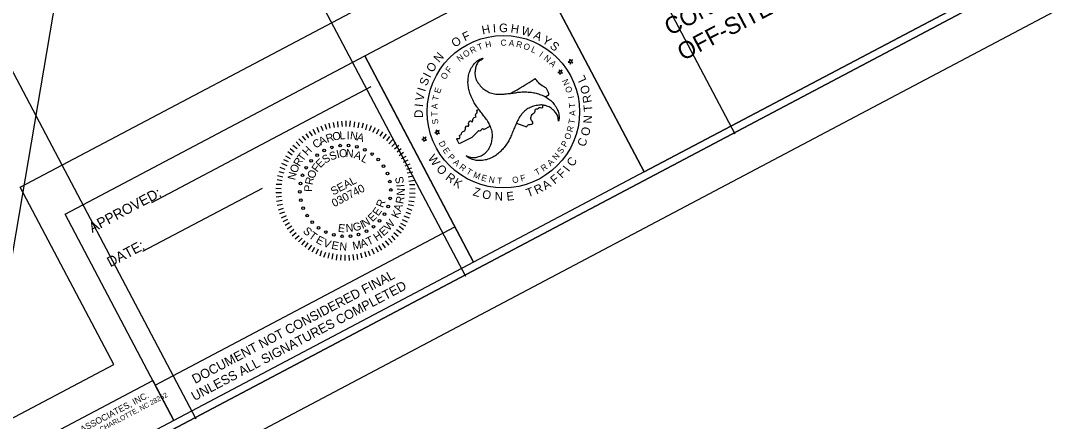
# Model space of a CAD drawing. Extents: x 1487176 to 2935813, y 497724 to 1002340.
# Drawn here: x 1489024 to 1489641, y 498480 to 498716 of the extents above; entities that cross this region are included whole.
import ezdxf

# ---------------------------------------------------------------- set-up
doc = ezdxf.new("R2010")
doc.units = 0
for name, color, linetype in [('DEV BORDER CELL', 7, 'Continuous'), ('DEV DOT SWIRL SEAL CELL', 7, 'Continuous'), ('Old_Level_9', 7, 'Continuous'), ('Prop Grid Mask', 7, 'Continuous'), ('Scratch_Level_0', 7, 'Continuous'), ('Scratch_Level_1', 7, 'Continuous'), ('Scratch_Level_3', 7, 'Continuous'), ('Scratch_Level_5', 7, 'Continuous'), ('Sheet Block Title CELL', 7, 'Continuous'), ('Sheet Plot Border Outside CELL', 7, 'Continuous'), ('Sheet Sticker Exception Certification CELL', 7, 'Continuous'), ('Text', 7, 'Continuous')]:
    doc.layers.add(name, color=color, linetype=linetype)

msp = doc.modelspace()

# ---------------------------------------------------------------- linework, layer by layer
at = {"layer": 'DEV BORDER CELL'}
for p, q in [((1489101.26, 498608.61), (1489230.66, 498676.94)), ((1489237.93, 498674.2), (1489291.16, 498573.39)), ((1489096.01, 498579.75), (1489166.57, 498617))]:
    msp.add_line(p, q, dxfattribs=at)
for points in [[(1489116.94, 499663.96), (1487790.49, 498963.57), (1488280.77, 498035.05), (1489607.21, 498735.45)], [(1489536.46, 498858.41), (1489327.77, 498748.22), (1489391.98, 498626.62), (1489600.67, 498736.82)], [(1489226.96, 498694.98), (1489327.77, 498748.22), (1489391.98, 498626.62), (1489291.16, 498573.39)], [(1489050.07, 498601.58), (1489226.96, 498694.98), (1489291.16, 498573.39), (1489114.27, 498479.99)]]:
    msp.add_lwpolyline(points, close=True, dxfattribs=at)
at = {"layer": 'DEV DOT SWIRL SEAL CELL'}
for p, q in [((1489347.93, 498691.91), (1489346.97, 498691.41)), ((1489346.97, 498691.41), (1489348.05, 498691.25)), ((1489348.53, 498692.23), (1489347.74, 498692.95)), ((1489347.74, 498692.95), (1489347.93, 498691.91)), ((1489348.05, 498691.25), (1489348.25, 498690.18)), ((1489348.25, 498690.18), (1489348.7, 498691.14)), ((1489349.49, 498692.74), (1489348.53, 498692.23)), ((1489348.7, 498691.14), (1489349.78, 498690.99)), ((1489349.01, 498691.76), (1489349.49, 498692.74)), ((1489349.78, 498690.99), (1489349.01, 498691.76)), ((1489341.84, 498685.71), (1489340.88, 498685.21)), ((1489340.88, 498685.21), (1489341.96, 498685.05)), ((1489342.45, 498686.03), (1489341.66, 498686.75)), ((1489341.66, 498686.75), (1489341.84, 498685.71)), ((1489341.96, 498685.05), (1489342.17, 498683.98)), ((1489342.17, 498683.98), (1489342.61, 498684.94)), ((1489343.4, 498686.54), (1489342.45, 498686.03)), ((1489342.61, 498684.94), (1489343.69, 498684.78)), ((1489342.92, 498685.56), (1489343.4, 498686.54)), ((1489343.69, 498684.78), (1489342.92, 498685.56)), ((1489269.86, 498650.52), (1489269.07, 498651.24)), ((1489269.07, 498651.24), (1489269.26, 498650.2)), ((1489270.82, 498651.02), (1489269.86, 498650.52)), ((1489270.34, 498650.04), (1489270.82, 498651.02)), ((1489297.33, 498651.57), (1489301.07, 498653.51)), ((1489316.53, 498655.36), (1489322.52, 498653.24)), ((1489261.58, 498646.16), (1489260.62, 498645.65)), ((1489260.62, 498645.65), (1489261.7, 498645.5)), ((1489262.18, 498646.48), (1489261.39, 498647.2)), ((1489261.39, 498647.2), (1489261.58, 498646.16)), ((1489261.7, 498645.5), (1489261.9, 498644.42)), ((1489261.9, 498644.42), (1489262.35, 498645.39)), ((1489263.14, 498646.98), (1489262.18, 498646.48)), ((1489262.35, 498645.39), (1489263.43, 498645.23)), ((1489262.35, 498645.39), (1489263.43, 498645.23)), ((1489262.66, 498646), (1489263.14, 498646.98)), ((1489262.66, 498646), (1489263.14, 498646.98)), ((1489263.43, 498645.23), (1489262.66, 498646)), ((1489263.43, 498645.23), (1489262.66, 498646)), ((1489269.26, 498650.2), (1489268.3, 498649.69)), ((1489268.3, 498649.69), (1489269.38, 498649.54)), ((1489269.38, 498649.54), (1489269.58, 498648.47)), ((1489269.58, 498648.47), (1489270.03, 498649.43)), ((1489270.03, 498649.43), (1489271.11, 498649.27)), ((1489271.11, 498649.27), (1489270.34, 498650.04)), ((1489282.63, 498643.21), (1489281.47, 498645.59)), ((1489290.2, 498646.85), (1489282.63, 498643.21)), ((1489293.79, 498650.34), (1489290.2, 498646.85))]:
    msp.add_line(p, q, dxfattribs=at)
for start, end in [(299.03861, 303.15865), (293.51358, 293.81132)]:
    msp.add_arc((1489200.02, 498876.84), 233.19, start, end, dxfattribs=at)
for points in [[(1489286.78, 498636.22), (1489289.27, 498635.26), (1489291.84, 498635.04), (1489294.35, 498635.64), (1489296.92, 498636.81), (1489299.15, 498638.74), (1489300.38, 498640.49), (1489300.79, 498641.43), (1489301.51, 498643.06), (1489301.89, 498644.47), (1489302.26, 498647.34), (1489302.09, 498650.41), (1489301.08, 498653.48), (1489300.97, 498653.74), (1489299.55, 498656.38), (1489297.77, 498658.88), (1489296.03, 498661.26), (1489294.14, 498663.69), (1489292.31, 498666.13), (1489290.89, 498668.69), (1489289.49, 498671.75), (1489288.58, 498674.51), (1489288.03, 498677.56), (1489287.83, 498679.03), (1489287.92, 498680.36), (1489288.22, 498683.52), (1489289.24, 498686.48), (1489290.04, 498688.18), (1489290.95, 498689.51), (1489291.1, 498689.74), (1489293.19, 498691.88), (1489295.61, 498693.28), (1489296.55, 498693.5)], [(1489296.58, 498693.61), (1489296.55, 498693.5), (1489294.5, 498691.88), (1489293, 498689.72), (1489292.26, 498687.26), (1489292, 498684.48), (1489292.57, 498681.56), (1489293.44, 498679.63), (1489294.08, 498678.81), (1489295.12, 498677.36), (1489296.13, 498676.31), (1489298.46, 498674.6), (1489301.18, 498673.18), (1489304.38, 498672.53), (1489304.64, 498672.49), (1489307.61, 498672.39), (1489310.7, 498672.68), (1489313.62, 498673.01), (1489316.65, 498673.43), (1489319.69, 498673.76), (1489322.63, 498673.73), (1489325.97, 498673.43), (1489328.8, 498672.83), (1489331.72, 498671.79), (1489333.12, 498671.22), (1489334.21, 498670.47), (1489336.81, 498668.65), (1489338.86, 498666.27), (1489339.95, 498664.72), (1489340.66, 498663.27), (1489340.78, 498663.04), (1489341.55, 498660.14), (1489341.54, 498657.34), (1489341.29, 498656.44)], [(1489333.54, 498670.95), (1489335.58, 498672.38), (1489335, 498674.27), (1489334.25, 498675.73), (1489332.47, 498676.93), (1489329.5, 498679.3), (1489327.56, 498681.63)], [(1489341.29, 498656.44), (1489340.89, 498659.03), (1489339.8, 498661.39), (1489338.01, 498663.27), (1489335.73, 498664.89), (1489332.95, 498665.85), (1489330.83, 498666.07), (1489329.79, 498665.91), (1489328.04, 498665.78), (1489326.58, 498665.37), (1489323.95, 498664.26), (1489321.35, 498662.58), (1489319.21, 498660.14), (1489319.04, 498659.94), (1489317.48, 498657.38), (1489316.18, 498654.6), (1489314.97, 498651.9), (1489313.83, 498649.05), (1489312.62, 498646.22), (1489311.12, 498643.73), (1489309.17, 498640.97), (1489307.24, 498638.83), (1489304.89, 498636.83), (1489303.69, 498635.89), (1489302.5, 498635.32), (1489299.65, 498634), (1489296.54, 498633.39), (1489294.68, 498633.23), (1489293.06, 498633.37), (1489292.78, 498633.38), (1489289.89, 498634.13), (1489287.49, 498635.53), (1489286.78, 498636.22)], [(1489322.52, 498653.24), (1489323.78, 498654.48), (1489325.28, 498654.67), (1489325.93, 498654.88), (1489326.24, 498655.52), (1489325.09, 498657.32), (1489325.06, 498658.42), (1489326.29, 498660.99), (1489327.39, 498661.92), (1489327.71, 498663.56), (1489328.1, 498663.73), (1489328.84, 498663.71), (1489329.99, 498664.63), (1489331.45, 498664.35), (1489332.02, 498664.71), (1489332.01, 498665.91)], [(1489281.47, 498645.59), (1489281.27, 498645.78), (1489281.54, 498646.24), (1489282.88, 498646.37), (1489283.18, 498647.14), (1489282.9, 498647.6), (1489283.1, 498648.31), (1489283.93, 498648.55), (1489284.16, 498649.76), (1489284.69, 498650.27), (1489286.01, 498650.97), (1489286.76, 498653.37), (1489287.35, 498653.81), (1489287.75, 498653.48), (1489288.19, 498653.62), (1489288.21, 498655.29), (1489288.29, 498655.55), (1489289.22, 498656.68), (1489289.68, 498656.61), (1489290.08, 498656.09), (1489290.31, 498656.08), (1489290.57, 498656.56), (1489290.75, 498657.56), (1489291.47, 498658.61), (1489292.7, 498659.06), (1489292.39, 498660.12), (1489293.27, 498661.73), (1489293.26, 498662.43), (1489293.04, 498663.02)], [(1489297.33, 498651.57), (1489296.72, 498651.99), (1489296.03, 498651.84), (1489295.43, 498650.99), (1489294.82, 498650.69), (1489293.88, 498650.84), (1489293.79, 498650.34)]]:
    msp.add_spline(points, degree=3, dxfattribs=at)
at = {"layer": 'Old_Level_9'}
for p, q in [((1489196.36, 498651.8), (1489197.88, 498648.92)), ((1489198.68, 498653.02), (1489199.87, 498649.97)), ((1489200.96, 498653.8), (1489202.14, 498651.03)), ((1489203.45, 498654.69), (1489204.3, 498651.75)), ((1489205.79, 498655.36), (1489206.41, 498652.3)), ((1489208.24, 498655.81), (1489208.87, 498652.74)), ((1489210.91, 498656.37), (1489210.98, 498653.01)), ((1489213.26, 498656.48), (1489213.6, 498653.41)), ((1489215.71, 498656.64), (1489215.79, 498653.29)), ((1489218.4, 498656.65), (1489218.02, 498653.34)), ((1489220.92, 498656.14), (1489220.43, 498653.06)), ((1489223.39, 498655.75), (1489222.79, 498652.61)), ((1489225.92, 498655.25), (1489225.2, 498652.32)), ((1489228.23, 498654.63), (1489227.35, 498651.48)), ((1489230.71, 498653.68), (1489229.54, 498650.8)), ((1489233.08, 498652.67), (1489231.57, 498649.89)), ((1489235.23, 498651.54), (1489233.72, 498648.77)), ((1489188.1, 498646.02), (1489190.33, 498643.67)), ((1489189.97, 498647.57), (1489191.92, 498645.21)), ((1489192.11, 498649.13), (1489193.74, 498646.59)), ((1489194.16, 498650.35), (1489195.89, 498647.87)), ((1489237.44, 498650.3), (1489235.76, 498647.58)), ((1489239.59, 498648.9), (1489237.58, 498646.28)), ((1489241.47, 498647.48), (1489239.74, 498644.87)), ((1489243.58, 498645.63), (1489241.17, 498643.23)), ((1489181.45, 498638.55), (1489184.17, 498636.6)), ((1489182.97, 498640.48), (1489185.31, 498638.47)), ((1489184.38, 498642.36), (1489187.11, 498640.41)), ((1489186.35, 498644.25), (1489188.53, 498642)), ((1489245.35, 498643.88), (1489243, 498641.65)), ((1489247.01, 498642.07), (1489244.54, 498640.06)), ((1489248.45, 498640.15), (1489246.09, 498638.19)), ((1489178.92, 498633.96), (1489181.74, 498632.63)), ((1489180.05, 498636.11), (1489182.99, 498634.56)), ((1489249.9, 498637.94), (1489247.2, 498636.09)), ((1489251.24, 498635.68), (1489248.47, 498634.22)), ((1489252.35, 498633.58), (1489249.58, 498632.12)), ((1489176.17, 498626.86), (1489179.15, 498626.03)), ((1489176.84, 498629.33), (1489179.72, 498628.17)), ((1489177.85, 498631.7), (1489180.85, 498630.32)), ((1489253.46, 498631.2), (1489250.69, 498630.02)), ((1489254.46, 498628.76), (1489251.52, 498627.91)), ((1489255.24, 498626.49), (1489252.07, 498625.8)), ((1489175.16, 498622.08), (1489178.19, 498621.42)), ((1489175.44, 498624.49), (1489178.53, 498623.72)), ((1489255.8, 498624.09), (1489252.63, 498623.41)), ((1489256.3, 498621.53), (1489252.9, 498621.01)), ((1489174.43, 498617.03), (1489177.62, 498616.88)), ((1489174.43, 498614.35), (1489177.79, 498614.42)), ((1489174.71, 498619.44), (1489177.9, 498619.29)), ((1489256.59, 498618.86), (1489253.45, 498618.9)), ((1489256.7, 498613.83), (1489253.45, 498614.09)), ((1489256.69, 498616.51), (1489253.62, 498616.44)), ((1489174.6, 498611.89), (1489177.84, 498612.19)), ((1489174.82, 498609.33), (1489178.17, 498609.96)), ((1489256.13, 498609), (1489252.99, 498609.33)), ((1489256.64, 498611.53), (1489253.28, 498611.74)), ((1489175.27, 498606.88), (1489178.44, 498607.56)), ((1489175.94, 498604.26), (1489179, 498605.17)), ((1489176.72, 498601.99), (1489179.66, 498603.11)), ((1489254.23, 498601.64), (1489251.41, 498602.69)), ((1489255.02, 498603.89), (1489251.92, 498604.94)), ((1489255.63, 498606.48), (1489252.6, 498607.14)), ((1489177.73, 498599.55), (1489180.66, 498600.96)), ((1489178.72, 498597.39), (1489181.6, 498598.63)), ((1489179.95, 498595.07), (1489182.6, 498596.75)), ((1489251.14, 498594.63), (1489248.2, 498596.19)), ((1489252.15, 498597.01), (1489249.32, 498598.34)), ((1489253.39, 498599.21), (1489250.28, 498600.54)), ((1489181.23, 498592.92), (1489183.93, 498594.77)), ((1489182.62, 498590.82), (1489185.15, 498592.72)), ((1489184.11, 498588.79), (1489186.53, 498590.91)), ((1489185.89, 498587.04), (1489188.19, 498589.1)), ((1489246.75, 498588.5), (1489244.18, 498590.68)), ((1489248.38, 498590.49), (1489245.76, 498592.5)), ((1489249.73, 498592.48), (1489247.18, 498594.38)), ((1489187.77, 498585.35), (1489190.01, 498587.52)), ((1489189.82, 498583.6), (1489191.67, 498585.99)), ((1489191.7, 498582.19), (1489193.49, 498584.69)), ((1489193.8, 498580.61), (1489195.64, 498583.28)), ((1489237.03, 498580.4), (1489235.29, 498583.16)), ((1489239.12, 498581.79), (1489237.39, 498584.27)), ((1489241.27, 498583.34), (1489239.26, 498585.82)), ((1489243.08, 498585.01), (1489241.01, 498587.31)), ((1489244.94, 498586.56), (1489242.88, 498588.86)), ((1489195.84, 498579.43), (1489197.51, 498582.15)), ((1489198.33, 498578.2), (1489199.61, 498581.13)), ((1489200.59, 498577.13), (1489201.64, 498580.23)), ((1489202.84, 498576.34), (1489203.95, 498579.33)), ((1489205.43, 498575.73), (1489206.09, 498578.76)), ((1489207.73, 498575.11), (1489208.28, 498578.36)), ((1489210.26, 498574.61), (1489210.69, 498577.8)), ((1489212.89, 498574.44), (1489213.05, 498577.63)), ((1489215.36, 498574.33), (1489215.34, 498577.57)), ((1489217.87, 498574.38), (1489217.8, 498577.46)), ((1489220.44, 498574.61), (1489220.14, 498577.84)), ((1489222.95, 498574.94), (1489222.43, 498578.06)), ((1489225.5, 498575.73), (1489224.65, 498578.67)), ((1489227.89, 498576.28), (1489226.99, 498579.34)), ((1489230.17, 498577.06), (1489229.1, 498579.89)), ((1489232.61, 498578.06), (1489231.2, 498581)), ((1489234.99, 498579.18), (1489233.53, 498581.94))]:
    msp.add_line(p, q, dxfattribs=at)
for centre in [(1489203.02, 498639.18), (1489207.6, 498641.06), (1489212.46, 498642.07), (1489217.41, 498642.17), (1489222.3, 498641.35), (1489226.96, 498639.66), (1489195.26, 498633.07), (1489198.85, 498636.49), (1489231.22, 498637.13), (1489234.95, 498633.86), (1489192.35, 498629.06), (1489238.02, 498629.97), (1489240.32, 498625.58), (1489188.97, 498619.79), (1489190.23, 498624.58), (1489241.77, 498620.84), (1489188.61, 498614.84), (1489242.32, 498615.91), (1489189.17, 498609.92), (1489241.96, 498610.97), (1489190.62, 498605.18), (1489192.92, 498600.78), (1489238.58, 498601.69), (1489240.7, 498606.18), (1489195.98, 498596.89), (1489235.67, 498597.68), (1489199.71, 498593.62), (1489203.98, 498591.1), (1489208.63, 498589.4), (1489213.52, 498588.59), (1489218.48, 498588.69), (1489223.33, 498589.69), (1489227.92, 498591.58), (1489232.08, 498594.27)]:
    msp.add_circle(centre, 0.788, dxfattribs=at)
at = {"layer": 'Prop Grid Mask'}
msp.add_lwpolyline([(1488938.22, 498417.14), (1489101.84, 498503.54), (1489114.27, 498479.99), (1488950.65, 498393.59)], close=True, dxfattribs=at)
at = {"layer": 'Scratch_Level_0'}
msp.add_lwpolyline([(1489096.07, 499596.4), (1487858.05, 498942.7), (1488301.64, 498102.61), (1489078.8, 498512.98), (1489023.58, 498617.56), (1489484.43, 498860.9)], close=True, dxfattribs=at)
at = {"layer": 'Scratch_Level_1'}
for p, q in [((1488905.4, 499671.94), (1489445.51, 498649.05)), ((1488746.22, 499587.89), (1489286.34, 498565)), ((1488587.05, 499503.85), (1489127.16, 498480.95)), ((1489085.53, 498970.89), (1488904.96, 497908.56))]:
    msp.add_line(p, q, dxfattribs=at)
at = {"layer": 'Scratch_Level_3'}
msp.add_lwpolyline([(1487790.49, 498963.57), (1488958.91, 499581.53), (1489116.94, 499663.96), (1489607.21, 498735.45), (1488280.77, 498035.05)], close=True, dxfattribs=at)
at = {"layer": 'Scratch_Level_5'}
msp.add_lwpolyline([(1489327.77, 498748.22), (1489536.46, 498858.41), (1489600.67, 498736.82), (1489391.98, 498626.62)], close=True, dxfattribs=at)
at = {"layer": 'Sheet Block Title CELL'}
msp.add_lwpolyline([(1488938.22, 498417.14), (1489101.84, 498503.54), (1489114.27, 498479.99), (1488950.65, 498393.59)], close=True, dxfattribs=at)
at = {"layer": 'Sheet Plot Border Outside CELL'}
msp.add_lwpolyline([(1488148.3, 497936.84), (1489640.99, 498725.01), (1489127.37, 499697.74), (1487634.68, 498909.56)], close=True, dxfattribs=at)
at = {"layer": 'Sheet Sticker Exception Certification CELL'}
for p, q in [((1489103.3, 498500.77), (1489280.19, 498594.17)), ((1489280.2, 498594.16), (1489291.17, 498573.38)), ((1489291.16, 498573.39), (1489114.27, 498479.99)), ((1489114.27, 498479.99), (1489103.3, 498500.77))]:
    msp.add_line(p, q, dxfattribs=at)
at = {"layer": 'Text'}
msp.add_circle((1489308.79, 498662.09), 44.97, dxfattribs=at)

# ---------------------------------------------------------------- texts
at = {"layer": 'DEV BORDER CELL'}
for s, height, p in [('CONTROL DETAILS', 10, (1489407.21, 498706.76)), ('OFF-SITE DETOUR', 10, (1489414.88, 498691.96)), ('APPROVED:  ', 6, (1489066.05, 498590.51)), ('DATE:  ', 6, (1489076.75, 498570.26))]:
    msp.add_text(s, height=height, rotation=27.83509, dxfattribs=at).set_placement(p)
at = {"layer": 'DEV DOT SWIRL SEAL CELL'}
for s, height, rotation, p in [('H', 5.04, 11.28908, (1489296.55, 498707.64)), ('I', 5.04, 3.63913, (1489302.72, 498708.78)), ('G', 5.04, 359.35179, (1489306.23, 498709.06)), ('H', 5.04, 351.29832, (1489312.83, 498708.88)), ('W', 5.04, 343.64837, (1489319.02, 498707.85)), ('F', 5.04, 25.09262, (1489286.01, 498703.54)), ('A', 5.04, 334.61134, (1489326.08, 498705.58)), ('Y', 5.04, 327.58347, (1489331.27, 498703.07)), ('O', 5.04, 33.60004, (1489280.12, 498699.8)), ('R', 3.63, 26.70157, (1489290.08, 498696.24)), ('H', 3.63, 11.46732, (1489298.5, 498699.72)), ('C', 3.63, 1.31115, (1489307.15, 498700.98)), ('A', 3.63, 351.15498, (1489311.76, 498701.01)), ('R', 3.63, 346.0769, (1489316.05, 498700.39)), ('O', 3.63, 340.99881, (1489320.24, 498699.31)), ('L', 3.63, 335.92073, (1489324.8, 498697.56)), ('S', 5.04, 321.05999, (1489335.78, 498700.18)), ('N', 5.04, 49.42115, (1489270.9, 498690.71)), ('N', 3.63, 36.85774, (1489282.92, 498691.34)), ('O', 3.63, 31.77966, (1489286.25, 498693.91)), ('I', 3.63, 325.76456, (1489329.6, 498695)), ('N', 3.63, 320.68647, (1489332.3, 498693.14)), ('O', 5.04, 57.92857, (1489267.07, 498684.87)), ('F', 3.63, 52.092, (1489277.1, 498684.74)), ('A', 3.63, 315.60839, (1489335.61, 498690.3)), ('S', 5.04, 68.41994, (1489263.6, 498677)), ('I', 5.04, 62.21591, (1489265.48, 498681.73)), ('O', 3.63, 57.17008, (1489274.48, 498680.7)), ('I', 5.04, 72.70727, (1489262.61, 498673.62)), ('E', 3.63, 72.40434, (1489271.29, 498672.58)), ('N', 3.63, 115.56806, (1489348.03, 498678.67)), ('O', 3.63, 110.76198, (1489349.75, 498674.07)), ('V', 5.04, 79.41569, (1489261.57, 498668.21)), ('T', 3.63, 77.48242, (1489270.3, 498668.32)), ('I', 3.63, 100.60581, (1489350.54, 498670.25)), ('I', 5.04, 83.70303, (1489261.24, 498664.71)), ('A', 3.63, 87.63859, (1489269.9, 498663.6)), ('T', 3.63, 95.52772, (1489351.3, 498664.54)), ('D', 5.04, 91.29414, (1489261.31, 498658.48)), ('T', 3.63, 92.71668, (1489269.96, 498659.34)), ('S', 3.63, 97.79476, (1489270.49, 498654.94)), ('T', 3.63, 80.29347, (1489350.68, 498654.62)), ('A', 3.63, 90.44964, (1489351.35, 498659.66)), ('R', 3.63, 75.21538, (1489349.55, 498649.8)), ('D', 3.63, 298.1071, (1489270.36, 498643.73)), ('P', 3.63, 59.98113, (1489345.66, 498640.87)), ('O', 3.63, 70.1373, (1489347.95, 498645.26)), ('E', 3.63, 303.18518, (1489272.74, 498639.48)), ('S', 3.63, 54.90305, (1489343.09, 498636.9)), ('P', 3.63, 313.34135, (1489275.7, 498635.16)), ('A', 3.63, 318.41944, (1489278.84, 498631.78)), ('A', 3.63, 44.74688, (1489336.66, 498629.82)), ('N', 3.63, 49.82496, (1489340.06, 498633.18)), ('R', 3.63, 323.49752, (1489282.35, 498628.73)), ('T', 3.63, 328.57561, (1489286.42, 498625.9)), ('M', 3.63, 338.73178, (1489290.65, 498623.5)), ('T', 3.63, 29.51262, (1489328.52, 498624.37)), ('R', 3.63, 34.59071, (1489332.38, 498626.68)), ('E', 3.63, 343.80986, (1489295.38, 498621.68)), ('N', 3.63, 348.88795, (1489299.88, 498620.48)), ('T', 3.63, 359.04411, (1489305.15, 498619.6)), ('O', 3.63, 9.20028, (1489314.29, 498619.88)), ('F', 3.63, 14.27837, (1489319.33, 498620.87))]:
    msp.add_text(s, height=height, rotation=rotation, dxfattribs=at).set_placement(p)
at = {"layer": 'Old_Level_9'}
for s, height, rotation, p in [('C', 4.72, 32.77501, (1489197.96, 498640.2)), ('A', 4.72, 25.80995, (1489201.05, 498642.11)), ('R', 4.72, 17.85665, (1489204.81, 498643.82)), ('O', 4.72, 10.92189, (1489208.31, 498644.96)), ('L', 4.72, 3.581, (1489212.15, 498645.72)), ('I', 4.72, 358.64105, (1489216.18, 498645.86)), ('N', 4.72, 352.73893, (1489218.02, 498645.85)), ('A', 4.72, 344.84016, (1489221.89, 498645.2)), ('H', 4.72, 45.57844, (1489192.97, 498635.73)), ('S', 4.7, 20.87655, (1489207.01, 498633.24)), ('I', 4.7, 13.31716, (1489210.78, 498634.67)), ('O', 4.7, 5.70998, (1489212, 498635.03)), ('N', 4.7, 355.22811, (1489215.62, 498635.39)), ('A', 4.7, 341.77886, (1489220.17, 498634.82)), ('R', 4.72, 60.01054, (1489188.53, 498629.42)), ('T', 4.72, 53.27087, (1489190.36, 498632.37)), ('E', 4.7, 44.42402, (1489200.68, 498628.63)), ('S', 4.7, 32.30312, (1489203.53, 498631.27)), ('L', 4.7, 329.3674, (1489224.39, 498633.24)), ('N', 4.72, 75.90175, (1489185.79, 498621.48)), ('O', 4.72, 67.77931, (1489186.77, 498625.53)), ('O', 4.7, 66.08691, (1489196.91, 498622.12)), ('F', 4.7, 54.23505, (1489198.89, 498626.13)), ('R', 4.7, 77.58289, (1489196.09, 498618.58)), ('SEAL', 4.699, 27.83509, (1489208.35, 498612.66)), ('S', 4.72, 100.09298, (1489250.16, 498620)), ('P', 4.7, 87.95873, (1489195.84, 498614.77)), ('030740', 4.699, 27.83509, (1489208.93, 498605.67)), ('I', 4.72, 93.88149, (1489250.37, 498617.72)), ('N', 4.72, 87.20766, (1489250.46, 498612.4)), ('R', 4.7, 68.18435, (1489237.71, 498605.07)), ('R', 4.72, 78.98541, (1489249.63, 498607.38)), ('E', 4.7, 43.64078, (1489231.46, 498596.83)), ('E', 4.7, 54.9919, (1489234.91, 498600.2)), ('K', 4.72, 63.9761, (1489246.55, 498598.77)), ('A', 4.72, 71.35678, (1489248.13, 498602.82)), ('E', 4.7, 352.70428, (1489210.9, 498591.34)), ('N', 4.7, 3.89345, (1489215.82, 498591.11)), ('G', 4.7, 15.31634, (1489220.63, 498591.39)), ('I', 4.7, 23.45968, (1489225.46, 498592.95)), ('N', 4.7, 30.96288, (1489226.78, 498593.65)), ('W', 4.72, 49.84085, (1489241.27, 498591.51)), ('S', 4.72, 316.0471, (1489190.09, 498591.26)), ('T', 4.72, 323.45948, (1489193.46, 498588.07)), ('H', 4.72, 33.84631, (1489233.99, 498585.49)), ('E', 4.72, 41.99985, (1489238, 498588.43)), ('E', 4.72, 331.65758, (1489197.67, 498585.09)), ('V', 4.72, 339.76489, (1489202.03, 498582.89)), ('E', 4.72, 348.06633, (1489206.95, 498581.3)), ('N', 4.72, 356.16408, (1489211.83, 498580.44)), ('M', 4.72, 10.17213, (1489220.12, 498580.57)), ('A', 4.72, 18.01726, (1489225.02, 498581.7)), ('T', 4.72, 25.22168, (1489229.11, 498583.08))]:
    msp.add_text(s, height=height, rotation=rotation, dxfattribs=at).set_placement(p)
at = {"layer": 'Sheet Block Title CELL'}
for s, height, p in [('10735 DAVID TAYLOR DRIVE, SUITE 310   CHARLOTTE, NC 28262', 2.9167, (1489000.03, 498435.55)), ('A. MORTON THOMAS AND ASSOCIATES, INC.', 3.75, (1489003.02, 498442.55))]:
    msp.add_text(s, height=height, rotation=27.83461, dxfattribs=at).set_placement(p)
at = {"layer": 'Sheet Sticker Exception Certification CELL'}
for s, p in [('DOCUMENT NOT CONSIDERED FINAL', (1489126.76, 498501.46)), ('UNLESS ALL SIGNATURES COMPLETED', (1489126.39, 498491.31))]:
    msp.add_text(s, height=5.5, rotation=27.83509, dxfattribs=at).set_placement(p)
at = {"layer": 'Text'}
for s, height, rotation, p in [('T', 3.63, 21.62349, (1489294.28, 498698.2)), ('L', 5.04, 115.26408, (1489357.96, 498680.76)), ('O', 5.04, 106.82474, (1489360.17, 498673.34)), ('R', 5.04, 100.58696, (1489361.08, 498667.69)), ('T', 5.04, 94.7161, (1489361.38, 498662.31)), ('N', 5.04, 86.72707, (1489360.9, 498655)), ('O', 5.04, 78.28773, (1489359.3, 498647.43)), ('C', 5.04, 70.9158, (1489357, 498641.07)), ('W', 5.04, 305.98508, (1489263.95, 498634.6)), ('C', 5.04, 55.83839, (1489349.87, 498629.25)), ('O', 5.04, 314.9498, (1489268.78, 498627.95)), ('R', 5.04, 323.38915, (1489274.23, 498622.45)), ('F', 5.04, 45.59775, (1489343.38, 498622.47)), ('I', 5.04, 51.58536, (1489347.32, 498626.3)), ('K', 5.04, 329.62693, (1489278.74, 498618.93)), ('A', 5.04, 32.63852, (1489333.61, 498615.72)), ('F', 5.04, 39.61015, (1489339.06, 498619.08)), ('Z', 5.04, 344.00385, (1489290.4, 498612.82)), ('O', 5.04, 350.35838, (1489295.96, 498611.08)), ('N', 5.04, 358.79773, (1489303.59, 498609.75)), ('E', 5.04, 6.78675, (1489310.91, 498609.54)), ('T', 5.04, 20.52988, (1489323.34, 498611.55)), ('R', 5.04, 26.40074, (1489328.43, 498613.3))]:
    msp.add_text(s, height=height, rotation=rotation, dxfattribs=at).set_placement(p)

doc.saveas('drawing.dxf')
